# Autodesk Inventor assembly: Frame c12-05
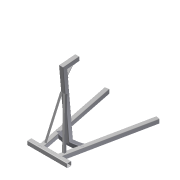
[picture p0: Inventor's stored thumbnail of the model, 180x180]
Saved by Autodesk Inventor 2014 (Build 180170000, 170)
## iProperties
Created: 2011-01
Part Number: Frame c12-05
Document SubType Name: Assembly
Designer: Thom Tremblay
_FrameDoc: Frame Assembly
_Version: 15.0.0
Author: Thom Tremblay
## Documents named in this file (20)
- C:\Inventor 2014 Essentials\Assemblies\Chapter 12\Frame\Frame c12-05.iam
- C:\Inventor 2014 Essentials\Assemblies\Chapter 12\Frame\Skeleton-c12-05.ipt
- C:\Inventor 2014 Essentials\Assemblies\Chapter 12\Frame\ANSI 2 1_4x5_16 00000001.ipt
- ANSI 2 1_4x5_16 00000001.ipt
- C:\Inventor 2014 Essentials\Assemblies\Chapter 12\Frame\ANSI 3x3x3_16 00000019.ipt
- ANSI 3x3x3_16 00000019.ipt
- C:\Inventor 2014 Essentials\Assemblies\Chapter 12\Frame\ANSI 3x3x3_16 00000020.ipt
- ANSI 3x3x3_16 00000020.ipt
- C:\Inventor 2014 Essentials\Assemblies\Chapter 12\Frame\ANSI 3x3x3_16 00000021.ipt
- ANSI 3x3x3_16 00000021.ipt
- C:\Inventor 2014 Essentials\Assemblies\Chapter 12\Frame\ANSI 3x3x3_16 00000022.ipt
- ANSI 3x3x3_16 00000022.ipt
- C:\Inventor 2014 Essentials\Assemblies\Chapter 12\Frame\ANSI 3x3x3_16 00000024.ipt
- ANSI 3x3x3_16 00000024.ipt
- C:\Inventor 2014 Essentials\Assemblies\Chapter 12\Frame\ANSI L 1.5 x 1.5 x 3_16 00000025.ipt
- ANSI L 1.5 x 1.5 x 3_16 00000025.ipt
- C:\Inventor 2014 Essentials\Assemblies\Chapter 12\Frame\ANSI L 1.5 x 1.5 x 3_16 00000026.ipt
- ANSI L 1.5 x 1.5 x 3_16 00000026.ipt
- C:\Inventor 2014 Essentials\Assemblies\Chapter 12\Frame\ANSI 3x3x3_16 00000058.ipt
- ANSI 3x3x3_16 00000058.ipt
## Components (10 placed, 10 different names)
1. Frame Reference Model
2. ANSI 2 1_4x5_16 00000001:1
3. ANSI 3x3x3_16 00000019:1
4. ANSI 3x3x3_16 00000020:1
5. ANSI 3x3x3_16 00000021:1
6. ANSI 3x3x3_16 00000022:1
7. ANSI 3x3x3_16 00000024:1
8. ANSI L 1.5 x 1.5 x 3_16 00000025:1
9. ANSI L 1.5 x 1.5 x 3_16 00000026:1
10. ANSI 3x3x3_16 00000058:1
